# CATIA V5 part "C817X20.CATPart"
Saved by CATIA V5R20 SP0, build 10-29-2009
Part number: C817X20
Source: Unknown
Property "A": "67.0"
Property "ARTICLENO": "C817XC20"
Property "B": "14"
Property "BOMINFO": "C817XC20"
Property "C": "17.0"
Property "CA": "C817XC20"
Property "D": "42"
Property "DES": "EYEBOLT TWISTER WITH BEARING M20 WITH KEY"
Property "E": "58"
Property "F": "40.0"
Property "K": "70"
Property "L": "30.0"
Property "LINA": "C817XC20"
Property "NB": "C817XC20"
Property "NBSYN": "$CODE."
Property "NN": "C817X"
Property "NT": "Eyebolt twister with bearing"
Property "SIZE": "M20"
Property "SUPPLIER": "CF"
Property "WEIGHT": "1150"
Property "WLL": "2.30"
Bounding box of the stored display mesh (mm): x -34.948 to 34.948, y -30 to 81, z -30.916 to 30.916
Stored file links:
  C:\Users\Utente\Desktop\3D files 817X\C817X20.CATPart
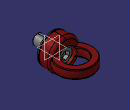
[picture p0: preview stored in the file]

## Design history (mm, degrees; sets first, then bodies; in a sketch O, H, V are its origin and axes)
Body1 "Geometry.1" (main body)
  Solid1 "C817XC20.catpart": solid without history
